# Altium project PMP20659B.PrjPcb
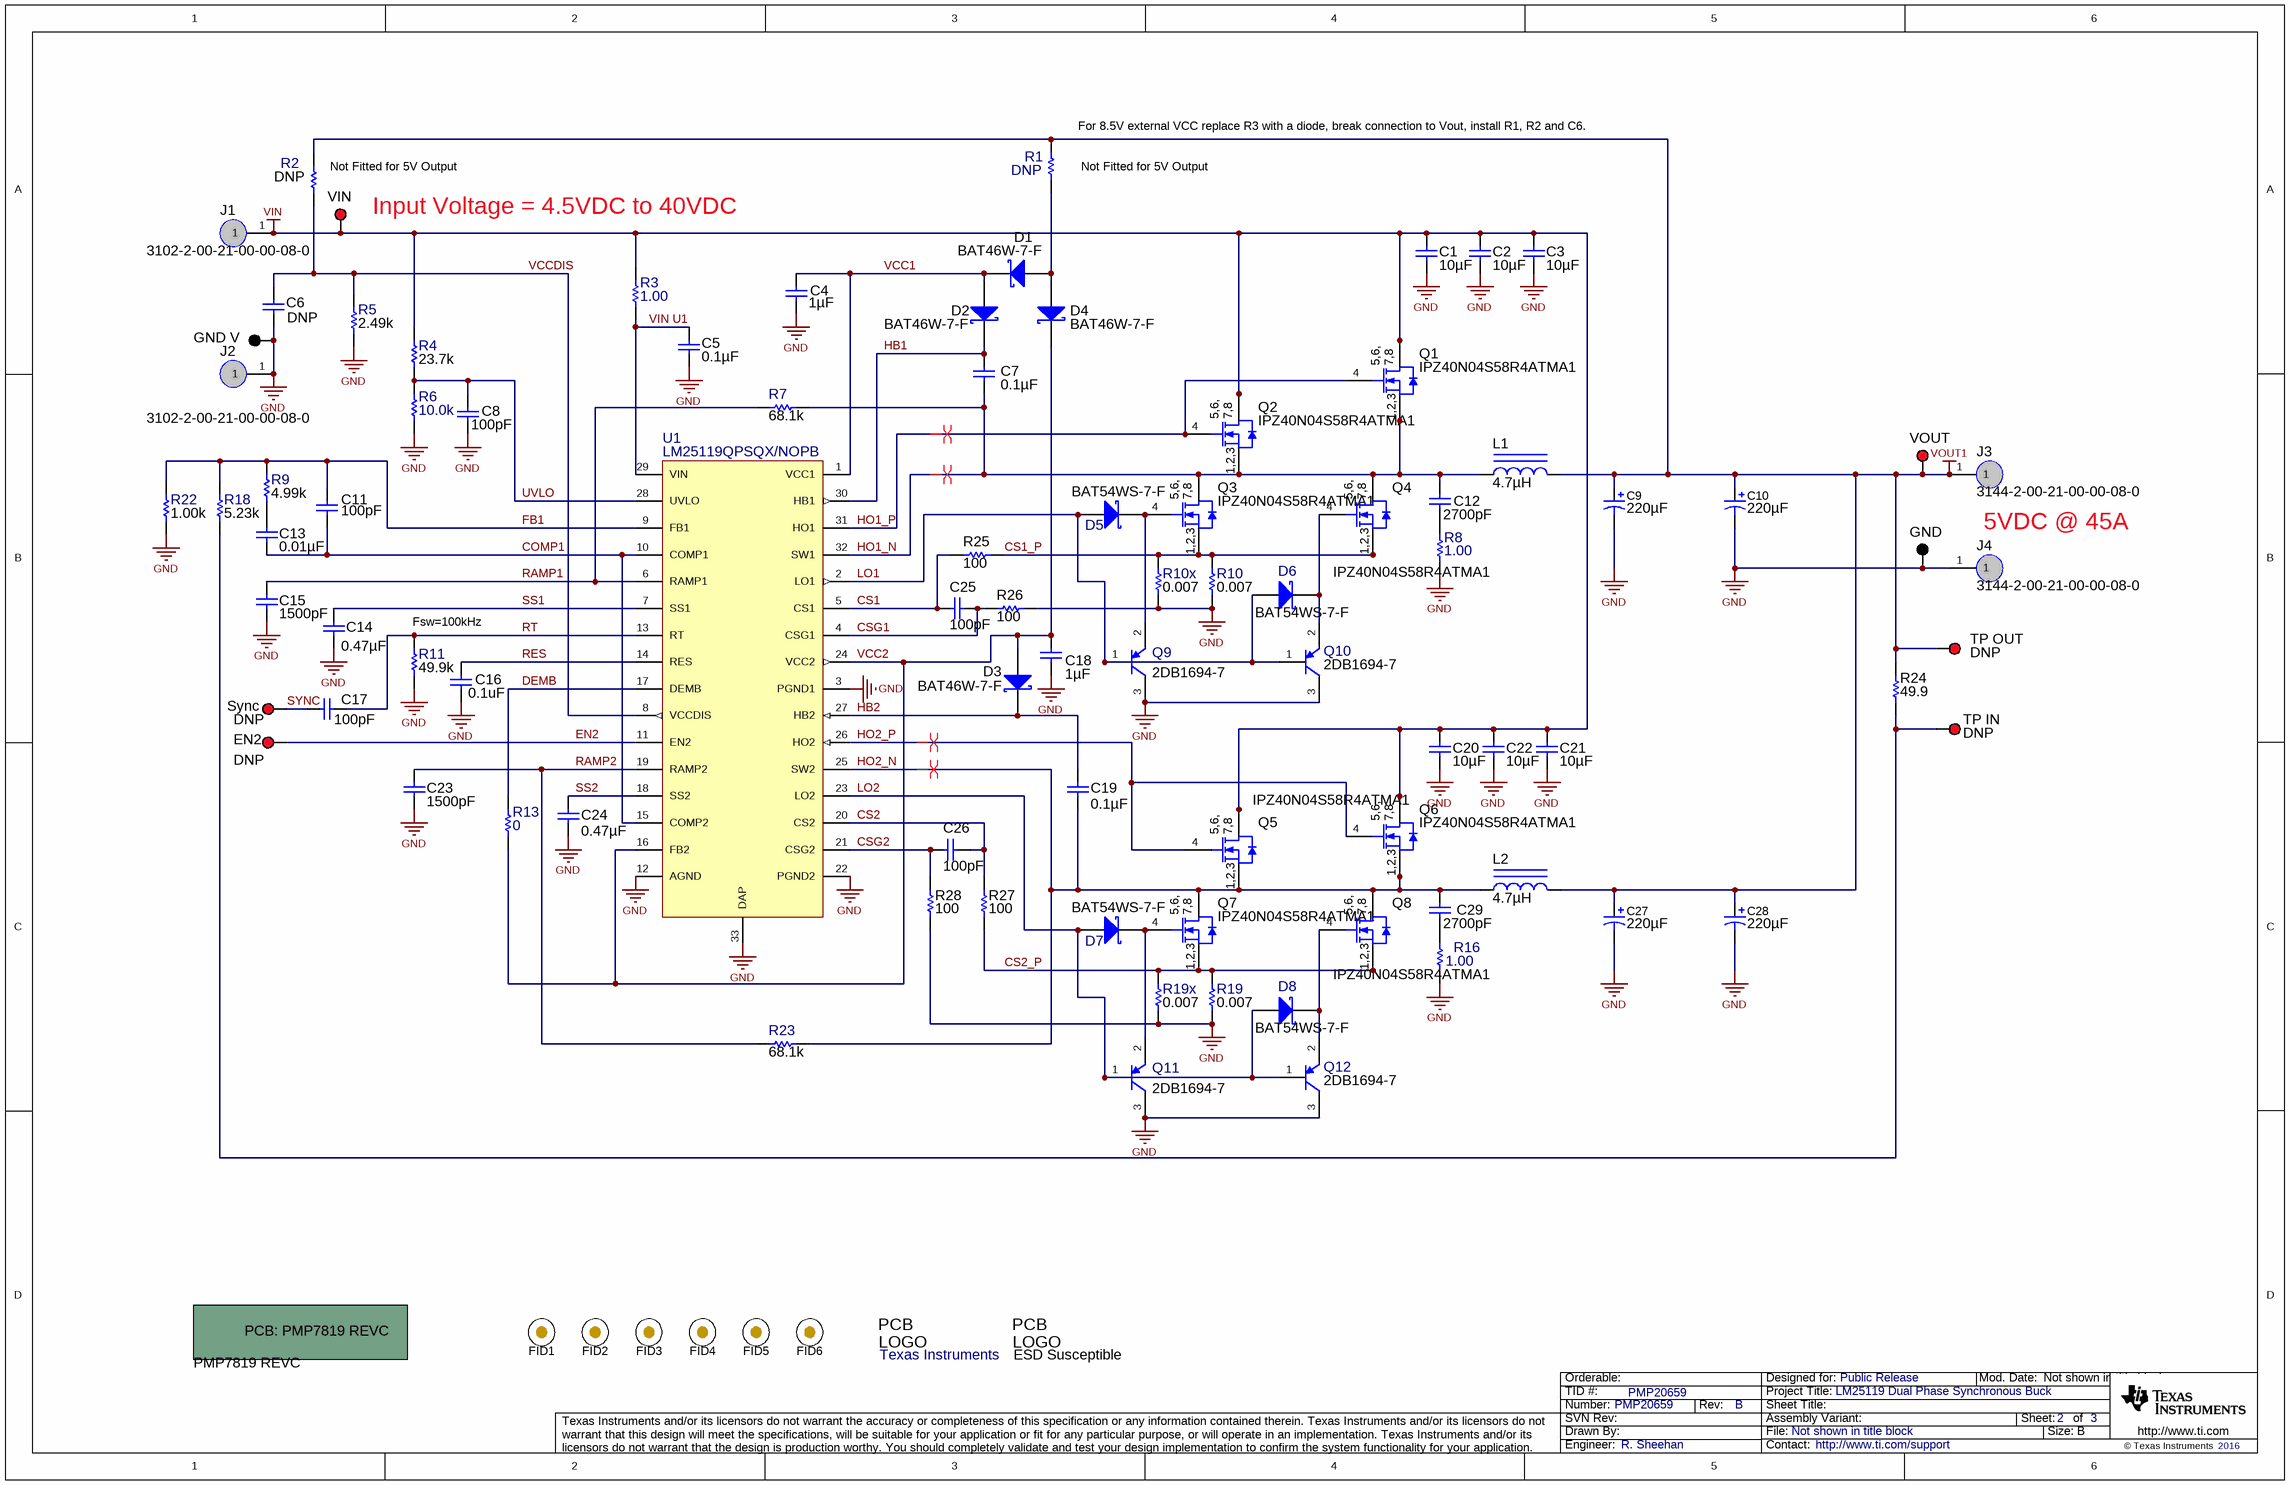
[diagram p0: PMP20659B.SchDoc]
TID: PMP20659; TechSupport: http://www.ti.com/support; SCH_Rev: B; PRJ_Title: LM25119 Dual Phase Synchronous Buck; PRJ_Number: PMP20659; PRJ_Engineer: R. Sheehan; PRJ_Customer: Public Release; PCB_Rev: C; CopyrightYear: 2016
1 sheet, 97 parts. Net scope: global (net labels, ports and power ports of the same name join across sheets).
Board file: PMP7819 REVC.PcbDoc

## Sheet PMP20659B.SchDoc
size 431 x 279 mm; Date: Not shown in title block; ApprovedBy: Not shown in title block; CheckedBy: Not shown in title block; Author: Not shown in title block; CompanyName: Not shown in title block; Engineer: Not shown in title block; Organization: Not shown in title block; Address1: Not shown in title block; Address2: Not shown in title block; Address3: Not shown in title block; Address4: Not shown in title block; DocumentNumber: 1; Revision: Use project parameter SCH_Rev; SheetNumber: 2; SheetTotal: 3; PageSetup: Record=PageOptions¦CenterHorizontal=True¦CenterVertical=True¦PrintScale=1.00¦XCorrection=1.00¦YCorrection=1.00¦PrintKind=0¦BorderSize=5000000¦LeftOffset=0¦BottomOffset=0¦Orientation=2¦PaperLength=1000¦PaperWidth=1000¦Scale=100¦PaperSource=15¦PrintQuality=600¦MediaType=1¦DitherType=10¦PaperKind=Letter¦PrintScaleMode=1

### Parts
!PCB?  PMP7819 REVC  (mechanical)
C1  ValueDisplayed: 10µF  [1210_280]  (hidden comment: UMK325AB7106KMHT)
C2  ValueDisplayed: 10µF  [1210_280]  (hidden comment: UMK325AB7106KMHT)
C3  ValueDisplayed: 10µF  [1210_280]  (hidden comment: UMK325AB7106KMHT)
C4  ValueDisplayed: 1µF  [0603]  (hidden comment: GRM188R71C105KA12D)
C5  ValueDisplayed: 0.1µF  [0805_HV]  (hidden comment: C2012X7R2A104K)
C6  DNP  [0603]
C7  ValueDisplayed: 0.1µF  [0603]  (hidden comment: GRM188R72A104KA35D)
C8  value 100pF  [0603]  (hidden comment: 06035A101JAT2A)
C9  ValueDisplayed: 220µF  [7343-31]  (hidden comment: T520D227M006ATE009)
C10  ValueDisplayed: 220µF  [7343-31]  (hidden comment: T520D227M006ATE009)
C11  value 100pF  [0603]  (hidden comment: 06035A101JAT2A)
C12  ValueDisplayed: 2700pF  [0603]  (hidden comment: 06031C272JAT2A)
C13  ValueDisplayed: 0.01µF  [0603]  (hidden comment: GCM188R71H103KA37D)
C14  ValueDisplayed: 0.47µF  [0603]  (hidden comment: GRM188R71E474KA12D)
C15  ValueDisplayed: 1500pF  [0603]  (hidden comment: GRM1885C1H152JA01D)
C16  value 0.1uF  [0603]  (hidden comment: C1608X7R1H104K)
C17  value 100pF  [0603]  (hidden comment: 06035A101JAT2A)
C18  ValueDisplayed: 1µF  [0603]  (hidden comment: GRM188R71C105KA12D)
C19  ValueDisplayed: 0.1µF  [0603]  (hidden comment: GRM188R72A104KA35D)
C20  ValueDisplayed: 10µF  [1210_280]  (hidden comment: UMK325AB7106KMHT)
C21  ValueDisplayed: 10µF  [1210_280]  (hidden comment: UMK325AB7106KMHT)
C22  ValueDisplayed: 10µF  [1210_280]  (hidden comment: UMK325AB7106KMHT)
C23  ValueDisplayed: 1500pF  [0603]  (hidden comment: GRM1885C1H152JA01D)
C24  ValueDisplayed: 0.47µF  [0603]  (hidden comment: GRM188R71E474KA12D)
C25  ValueDisplayed: 100pF  [0603]  (hidden comment: GRM1885C1H101JA01D)
C26  ValueDisplayed: 100pF  [0603]  (hidden comment: GRM1885C1H101JA01D)
C27  ValueDisplayed: 220µF  [7343-31]  (hidden comment: T520D227M006ATE009)
C28  ValueDisplayed: 220µF  [7343-31]  (hidden comment: T520D227M006ATE009)
C29  ValueDisplayed: 2700pF  [0603]  (hidden comment: 06031C272JAT2A)
D1  BAT46W-7-F  [SOD-123]
D2  BAT46W-7-F  [SOD-123]
D3  BAT46W-7-F  [SOD-123]
D4  BAT46W-7-F  [SOD-123]
D5  BAT54WS-7-F  [sod-323]
D6  BAT54WS-7-F  [sod-323]
D7  BAT54WS-7-F  [sod-323]
D8  BAT54WS-7-F  [sod-323]
EN2  DNP  [Keystone5000]
FID1  Fiducial  [Fiducial10-20]  (value not drawn)
FID2  Fiducial  [Fiducial10-20]  (value not drawn)
FID3  Fiducial  [Fiducial10-20]  (value not drawn)
FID4  Fiducial  [Fiducial10-20]  (value not drawn)
FID5  Fiducial  [Fiducial10-20]  (value not drawn)
FID6  Fiducial  [Fiducial10-20]  (value not drawn)
GND  5001  [Keystone5001]  (value not drawn)
GND_V  5001  [Keystone5001]  (value not drawn)
J1  3102-2-00-21-00-00-08-0  [3102-2-00-21-00-00-08-0]
J2  3102-2-00-21-00-00-08-0  [3102-2-00-21-00-00-08-0]
J3  3144-2-00-21-00-00-08-0  [3144-2-00-21-00-00-08-0]
J4  3144-2-00-21-00-00-08-0  [3144-2-00-21-00-00-08-0]
L1  ValueDisplayed: 4.7µH  [XAL1510]  (hidden comment: XAL1510-472MEB)
L2  ValueDisplayed: 4.7µH  [XAL1510]  (hidden comment: XAL1510-472MEB)
Logo1  Texas Instruments  [TI_Symbol_Overlay_Small]  (no BOM)
Logo2  ESD Susceptible  [ESD_Overlay_Small]  (no BOM)
Q1  IPZ40N04S58R4ATMA1  [PG-TSDSON-8]
Q2  IPZ40N04S58R4ATMA1  [PG-TSDSON-8]
Q3  IPZ40N04S58R4ATMA1  [PG-TSDSON-8]
Q4  IPZ40N04S58R4ATMA1  [PG-TSDSON-8]
Q5  IPZ40N04S58R4ATMA1  [PG-TSDSON-8]
Q6  IPZ40N04S58R4ATMA1  [PG-TSDSON-8]
Q7  IPZ40N04S58R4ATMA1  [PG-TSDSON-8]
Q8  IPZ40N04S58R4ATMA1  [PG-TSDSON-8]
Q9  2DB1694-7  [SOT-323 DIODES INC]
Q10  2DB1694-7  [SOT-323 DIODES INC]
Q11  2DB1694-7  [SOT-323 DIODES INC]
Q12  2DB1694-7  [SOT-323 DIODES INC]
R1  DNP  [0603]
R2  DNP  [0603]
R3  value 1.00  [0805_HV]  (hidden comment: CRCW08051R00FNEA)
R4  ValueDisplayed: 23.7k  [0603]  (hidden comment: CRCW060323K7FKEA)
R5  value 2.49k  [0603]  (hidden comment: CRCW06032K49FKEA)
R6  value 10.0k  [0603]  (hidden comment: CRCW060310K0FKEA)
R7  ValueDisplayed: 68.1k  [0603]  (hidden comment: CRCW060368K1FKEA)
R8  value 1.00  [1206]  (hidden comment: CRCW12061R00FNEA)
R9  ValueDisplayed: 4.99k  [0603]  (hidden comment: CRCW06034K99FKEA)
R10  ValueDisplayed: 0.007  [2010]  (hidden comment: WSL20107L000FEA18)
R10x  ValueDisplayed: 0.007  [2010]  (hidden comment: WSL20107L000FEA18)
R11  ValueDisplayed: 49.9k  [0603]  (hidden comment: CRCW060349K9FKEA)
R13  value 0  [0603]  (hidden comment: CRCW06030000Z0EA)
R16  value 1.00  [1206]  (hidden comment: CRCW12061R00FNEA)
R18  ValueDisplayed: 5.23k  [0603]  (hidden comment: CRCW06035K23FKEA)
R19  ValueDisplayed: 0.007  [2010]  (hidden comment: WSL20107L000FEA18)
R19x  ValueDisplayed: 0.007  [2010]  (hidden comment: WSL20107L000FEA18)
R22  ValueDisplayed: 1.00k  [0603]  (hidden comment: CRCW06031K00FKEA)
R23  ValueDisplayed: 68.1k  [0603]  (hidden comment: CRCW060368K1FKEA)
R24  value 49.9  [0603]  (hidden comment: CRCW060349R9FKEA)
R25  ValueDisplayed: 100  [0603]  (hidden comment: CRCW0603100RJNEA)
R26  ValueDisplayed: 100  [0603]  (hidden comment: CRCW0603100RJNEA)
R27  ValueDisplayed: 100  [0603]  (hidden comment: CRCW0603100RJNEA)
R28  ValueDisplayed: 100  [0603]  (hidden comment: CRCW0603100RJNEA)
Sync  DNP  [Keystone5000]
TP_IN  DNP  [Keystone5000]
TP_OUT  DNP  [Keystone5000]
U1  LM25119QPSQX/NOPB  [RTV0032A]
VIN  5000  [Keystone5000]  (value not drawn)
VOUT  5000  [Keystone5000]  (value not drawn)

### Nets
GND: C1.2 C2.2 C3.2 C4.2 C5.2 C6.2 C8.2 C9.2(-) C10.2(-) C14.2 C15.2 C16.2 C18.2 C20.2 C21.2 C22.2 C23.2 C24.2 C27.2(-) C28.2(-) GND.1 GND_V.1 J2.1 J4.1 Q9.3(C) Q10.3(C) Q11.3(C) Q12.3(C) R5.2 R6.1 R8.2 R10.1 R10x.1 R11.1 R16.2 R19.1 R19x.1 R22.1 R26.2 R28.1 U1.3(PGND1) U1.12(AGND) U1.22(PGND2) U1.33(DAP)
VIN: C1.1 C2.1 C3.1 C20.1 C21.1 C22.1 J1.1 Q1.5(D) Q1.6(D) Q1.7(D) Q1.8(D) Q1.9(D) Q2.5(D) Q2.6(D) Q2.7(D) Q2.8(D) Q2.9(D) Q5.5(D) Q5.6(D) Q5.7(D) Q5.8(D) Q5.9(D) Q6.5(D) Q6.6(D) Q6.7(D) Q6.8(D) Q6.9(D) R3.2 R4.2 VIN.1
VOUT1: C9.1(+) C10.1(+) C27.1(+) C28.1(+) J3.1 L1.2 L2.2 R1.1 R2.2 R24.2 TP_OUT.1 VOUT.1
COMP1: C11.2 C13.2 U1.10(COMP1) U1.15(COMP2)
CS1: C25.2 R25.1 U1.5(CS1)
CS1_P: Q3.1(S) Q3.2(S) Q3.3(S) Q4.1(S) Q4.2(S) Q4.3(S) R10.2 R10x.2 R25.2
CS2: C26.1 R27.2 U1.20(CS2)
CS2_P: Q7.1(S) Q7.2(S) Q7.3(S) Q8.1(S) Q8.2(S) Q8.3(S) R19.2 R19x.2 R27.1
CSG1: C25.1 R26.1 U1.4(CSG1)
CSG2: C26.2 R28.2 U1.21(CSG2)
DEMB: R13.2 U1.17(DEMB)
EN2: EN2.1 U1.11(EN2)
FB1: C11.1 R9.2 R18.1 R22.2 U1.9(FB1)
HB1: C7.2 D2.1(K) U1.30(HB1)
HB2: C19.1 D3.1(K) U1.27(HB2)
HO1_N: C7.1 C12.1 L1.1 Q1.1(S) Q1.2(S) Q1.3(S) Q2.1(S) Q2.2(S) Q2.3(S) Q3.5(D) Q3.6(D) Q3.7(D) Q3.8(D) Q3.9(D) Q4.5(D) Q4.6(D) Q4.7(D) Q4.8(D) Q4.9(D) R7.2 U1.32(SW1)
HO1_P: Q1.4(G) Q2.4(G) U1.31(HO1)
HO2_N: C19.2 C29.1 L2.1 Q5.1(S) Q5.2(S) Q5.3(S) Q6.1(S) Q6.2(S) Q6.3(S) Q7.5(D) Q7.6(D) Q7.7(D) Q7.8(D) Q7.9(D) Q8.5(D) Q8.6(D) Q8.7(D) Q8.8(D) Q8.9(D) R23.2 U1.25(SW2)
HO2_P: Q5.4(G) Q6.4(G) U1.26(HO2)
LO1: D5.2(A) D6.2(A) Q9.1(B) Q10.1(B) U1.2(LO1)
LO2: D7.2(A) D8.2(A) Q11.1(B) Q12.1(B) U1.23(LO2)
RAMP1: C15.1 R7.1 U1.6(RAMP1)
RAMP2: C23.1 R23.1 U1.19(RAMP2)
RES: C16.1 U1.14(RES)
RT: C17.2 R11.2 U1.13(RT)
SS1: C14.1 U1.7(SS1)
SS2: C24.1 U1.18(SS2)
SYNC: C17.1 Sync.1
UVLO: C8.1 R4.1 R6.2 U1.28(UVLO)
VCC1: C4.1 D1.1(K) D2.2(A) U1.1(VCC1)
VCC2: C18.1 D3.2(A) D4.1(K) R13.1 U1.16(FB2) U1.24(VCC2)
VCCDIS: C6.1 R2.1 R5.1 U1.8(VCCDIS)
VIN U1: C5.1 R3.1 U1.29(VIN)
NetC12_2: C12.2 R8.1
NetC13_1: C13.1 R9.1
NetC29_2: C29.2 R16.1
NetD1_2: D1.2(A) D4.2(A) R1.2
NetD5_1: D5.1(K) Q3.4(G) Q9.2(E)
NetD6_1: D6.1(K) Q4.4(G) Q10.2(E)
NetD7_1: D7.1(K) Q7.4(G) Q11.2(E)
NetD8_1: D8.1(K) Q8.4(G) Q12.2(E)
NetR18_2: R18.2 R24.1 TP_IN.1

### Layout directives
differential pair: HO1_N, HO1_P, HO2_N, HO2_P

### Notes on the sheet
- (near R2) Not Fitted for 5V Output
- (near R1) Not Fitted for 5V Output
- (near R1) For 8.5V external VCC replace R3 with a diode, break connection to Vout, install R1, R2 and C6.
- (near VIN) Input Voltage = 4.5VDC to 40VDC
- 5VDC @ 45A
- (near R11) Fsw=100kHz

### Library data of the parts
!PCB? = PCB_OtherProject: Manufacturer: Any; SymbolCreator: a0412235; CompType: PCB; U/M: EA
C1-C3 C20-C22 = UMK325AB7106KMHT: CAP, CERM, 10 µF, 50 V, +/- 10%, X7R, AEC-Q200 Grade 1, 1210; Manufacturer: Taiyo Yuden; Cap_Case: 1210; Polarized: N; TaMax_C: 125; TaMin_C: -55; Tolerance_%: 10; VDC_V: 50; Cap_F: 0.00001; CompType: Capacitor; Value: 10uF; Value1: Unknown; Value2: 50V; U/M: EA; SizeArea_mm2: 8; SizeAreaWB_mm2: 14.7; SizeX_mm: 3.2; SizeY_mm: 2.5; SizeZ_mm: 2.8; AEC Category: Q200; AEC Qualified: Y; AEC Grade: 1
C4 C18 = GRM188R71C105KA12D: CAP, CERM, 1uF, 16V, +/-10%, X7R, 0603; Manufacturer: MuRata; ESR_Ohm: 0.011; Polarized: N; TaMax_C: 125; TaMin_C: -55; Tolerance_%: 10; VDC_V: 16; Cap_F: 0.000001; CompType: Capacitor; U/M: EA; Value1: 0.011 ohm
C5 = C2012X7R2A104K: CAP, CERM, 0.1uF, 100V, +/-10%, X7R, 0805; Manufacturer: TDK; Cap_Case: 0805; ESR_Ohm: 0.0158; Polarized: N; TaMax_C: 125; TaMin_C: -55; Tolerance_%: 10; VDC_V: 100; Cap_F: 0.0000001; CompType: Capacitor; Value1: 0.0158 ohm; U/M: EA
C6 C16 = C1608X7R1H104K: CAP, CERM, 0.1uF, 50V, +/-10%, X7R, 0603; Manufacturer: TDK; ESR_Ohm: 0.017; Polarized: N; TaMax_C: 125; TaMin_C: -55; Tolerance_%: 10; VDC_V: 50; Cap_F: 0.0000001; CompType: Capacitor; Value1: 0.017 ohm; U/M: EA; ValueDisplayed: 0.1µF
C7 C19 = GRM188R72A104KA35D: CAP, CERM, 0.1uF, 100V, +/-10%, X7R, 0603; Manufacturer: MuRata; Polarized: N; TaMax_C: 125; TaMin_C: -55; Tolerance_%: 10; VDC_V: 100; Cap_F: 0.0000001; CompType: Capacitor; U/M: EA
C8 C11 C17 = 06035A101JAT2A: CAP, CERM, 100pF, 50V, +/-5%, C0G/NP0, 0603; Manufacturer: AVX; ESR_Ohm: 0.119; Polarized: N; TaMax_C: 125; TaMin_C: -55; Tolerance_%: 5; VDC_V: 50; Cap_F: 0.0000000001; CompType: Capacitor; Value1: 0.119 ohm; U/M: EA
C9 C10 C27 C28 = T520D227M006ATE009: CAP, TA, 220 µF, 6.3 V, +/- 20%, 0.009 ohm, SMD; Manufacturer: Kemet; Polarized: Y; CompType: Capacitor; Value: 220uF; U/M: EA; Cap_F: 0.00022; Tolerance_%: 20; VDC_V: 6.3; Value2: 6.3V; ESR_ohm: 0.009; TaMin_C: -55; TaMax_C: 105; Cap_Case: D; SizeAreaWB_mm2: 58.59; SizeArea_mm2: 31.39; SizeX_mm: 7.3; SizeY_mm: 4.3; SizeZ_mm: 3.1; AEC Category: Q200; AEC Qualified: N
C12 C29 = 06031C272JAT2A: CAP, CERM, 2700pF, 100V, +/-5%, X7R, 0603; Manufacturer: AVX; ESR_Ohm: 0.174; Polarized: N; TaMax_C: 125; TaMin_C: -55; Tolerance_%: 5; VDC_V: 100; Cap_F: 0.0000000027; CompType: Capacitor; Value1: 0.174 ohm; U/M: EA
C13 = GCM188R71H103KA37D: CAP, CERM, 0.01 µF, 50 V, +/- 10%, X7R, AEC-Q200 Grade 1, 0603; Manufacturer: MuRata; Polarized: N; TaMax_C: 125; TaMin_C: -55; Tolerance_%: 10; VDC_V: 50; Cap_F: 0.00000001; CompType: Capacitor; Value: 0.01uF; Value1: Unknown; Value2: 50V; U/M: EA; SizeArea_mm2: 1.28; SizeAreaWB_mm2: 4.68; SizeX_mm: 1.6; SizeY_mm: 0.8; SizeZ_mm: 1; AEC Category: Q200; AEC Qualified: Y
C14 C24 = GRM188R71E474KA12D: CAP, CERM, 0.47uF, 25V, +/-10%, X7R, 0603; Manufacturer: MuRata; Polarized: N; TaMax_C: 125; TaMin_C: -55; Tolerance_%: 10; VDC_V: 25; Cap_F: 0.00000047; CompType: Capacitor; Value1: Unknown; U/M: EA
C15 C23 = GRM1885C1H152JA01D: CAP, CERM, 1500 pF, 50 V, +/- 5%, C0G/NP0, 0603; Manufacturer: MuRata; Polarized: N; TaMax_C: 125; TaMin_C: -55; Tolerance_%: 5; VDC_V: 50; Cap_F: 0.0000000015; CompType: Capacitor; Value: 1500pF; Value1: Unknown; Value2: 50V; U/M: EA; SizeArea_mm2: 1.28; SizeAreaWB_mm2: 4.68; SizeX_mm: 1.6; SizeY_mm: 0.8; SizeZ_mm: 1; AEC Category: Q200
C25 C26 = GRM1885C1H101JA01D: CAP, CERM, 100 pF, 50 V, +/- 5%, C0G/NP0, 0603; Manufacturer: MuRata; Polarized: N; CompType: Capacitor; Value: 100pF; U/M: EA; Cap_F: 0.0000000001; Tolerance_%: 5; Value1: Unknown; VDC_V: 50; Value2: 50V; TaMin_C: -55; TaMax_C: 125; SizeArea_mm2: 1.28; SizeAreaWB_mm2: 4.68; SizeX_mm: 1.6; SizeY_mm: 0.8; SizeZ_mm: 1; AEC Category: Q200
D1-D4 = BAT46W-7-F: Diode, Schottky, 100V, 0.15A, SOD-123; Manufacturer: Diodes Inc.; Vf_V: 0.6; Io_A: 0.15; Vr_V: 100; Value: 0.6V; U/M: EA
D5-D8 = BAT54WS-7-F: Diode, Schottky, 30V, 0.2A, SOD-323; Manufacturer: Diodes Inc.; Value: 0.7V; U/M: EA; Vf_V: 0.7; Io_A: 0.2; Vr_V: 30; TJmax_C: 125
EN2 Sync TP_IN TP_OUT VIN VOUT = 5000: Test Point, TH, Miniature, Red; Manufacturer: Keystone; CompType: Test Point Loop; U/M: EA
FID1-FID6 = Fiducial: Fiducial mark.  There is nothing to buy or mount.; SymbolCreator: codlsc
GND GND_V = 5001: Test Point, TH, Miniature, Black; Manufacturer: Keystone; CompType: Test Point Loop; U/M: EA
J1 J2 = 3102-2-00-21-00-00-08-0: PC PIN .040 DIA 3102-2 SERIES; Manufacturer: Mill -Max; SymbolVersion: 2011 - 12 - 16; SymbolCreator: cdnlsc; U/M: EA
J3 J4 = 3144-2-00-21-00-00-08-0: CIRCUIT PIN PRNTD .188" .084"; Manufacturer: Mill -Max; SymbolVersion: 2011 - 12 - 16; SymbolCreator: cdnlsc; U/M: EA
L1 L2 = XAL1510-472MEB: Inductor, Shielded, Composite, 4.7 µH, 29 A, 0.00335 ohm, SMD; Manufacturer: Coilcraft; Value: 4.7uH; Ind_H: 4.7E-6; Imax_A: 29; Irms: 29A @ 40C rise; Isat: 39A @ 30% inductance drop; Value2: 29A; SizeAreaWB_mm2: 320.16; SizeArea_mm2: 252.56; SizeX_mm: 16.4; SizeY_mm: 15.4; SizeZ_mm: 10; AEC Category: Q200
Logo1 = TI_Logo: Texas Instrument Corporate Signature; SymbolCreator: codlsc
Logo2 = ESD_Susceptible: ESD Susceptible Symbol; SymbolCreator: codlsc
Q1-Q8 = IPZ40N04S58R4ATMA1: MOSFET, N-CH, 40 V, 40 A, AEC-Q101, PG-TSDSON-8; Manufacturer: Infineon Technologies; Alternate Manufacturer: None; Value: 40V; ChType: N; VdsMax_V: 40; Value1: ? ohm; Value2: 10.3 nC; QgTyp_nC: 10.3; Vgs_V: 20; U/M: EA; SizeAreaWB_mm2: 19.36; SizeArea_mm2: 11.56; SizeX_mm: 3.4; SizeZ_mm: 1.1; AEC Category: Q101; AEC Qualified: Y
Q9-Q12 = 2DB1694-7: TRANS BIPO PNP 30V 1A SOT-323; Manufacturer: Diodes Inc.; CompType: BJT; U/M: EA; PNP: 1; NPN: 0; Vceo_V: 30; Vcesat1_V: 0.075; Value: 0.075V; IcRated_A: 0.1; Value1: 0.1A; HfeMax: 600
R1 = CRCW06030000Z0EA: RES, 0 ohm, 5%, 0.1W, 0603; Manufacturer: Vishay-Dale; CompType: Resistor; Tolerance_%: 5; VDC_V: 75; Power_W: 0.1; Res_Ohm: 0; Value: 0; Value_Code: 0000; EIA_Code: E24; U/M: EA
R2 = CRCW060310K0FKEA: RES, 10.0k ohm, 1%, 0.1W, 0603; Manufacturer: Vishay-Dale; CompType: Resistor; Tolerance_%: 1; VDC_V: 75; Power_W: 0.1; Res_ohm: 10000; Value_Code: 10k0; EIA_Code: E96; U/M: EA; TempCo: 100 ppm/C
R3 = CRCW08051R00FNEA: RES, 1.00 ohm, 1%, 0.125W, 0805; Manufacturer: Vishay-Dale; CompType: Resistor; Tolerance_%: 1; VDC_V: 150; Power_W: 0.125; Value_Code: 1R00; EIA_Code: E96; U/M: EA
R4 = CRCW060323K7FKEA: RES, 23.7 k, 1%, 0.1 W, 0603; Manufacturer: Vishay-Dale; CompType: Resistor; Tolerance_%: 1; VDC_V: 75; Power_W: 0.1; Res_ohm: 23700; Value: 23.7k; Value_Code: 23k7; Value2: 0.1W; EIA_Code: E96; U/M: EA; TempCo: 100 ppm/C; SizeArea_mm2: 1.28; SizeX_mm: 1.6; SizeY_mm: 0.8; AEC Category: Q200
R5 = CRCW06032K49FKEA: RES, 2.49k ohm, 1%, 0.1W, 0603; Manufacturer: Vishay-Dale; CompType: Resistor; Tolerance_%: 1; VDC_V: 75; Power_W: 0.1; Res_ohm: 2490; Value_Code: 2k49; EIA_Code: E96; U/M: EA; TempCo: 100 ppm/C
R6 = CRCW060310K0FKEA: RES, 10.0k ohm, 1%, 0.1W, 0603; Manufacturer: Vishay-Dale; CompType: Resistor; Tolerance_%: 1; VDC_V: 75; Power_W: 0.1; Res_Ohm: 10000; Value_Code: 10k0; EIA_Code: E96; U/M: EA
R7 R23 = CRCW060368K1FKEA: RES, 68.1 k, 1%, 0.1 W, 0603; Manufacturer: Vishay-Dale; CompType: Resistor; Tolerance_%: 1; VDC_V: 75; Power_W: 0.1; Res_ohm: 68100; Value: 68.1k; Value_Code: 68k1; Value2: 0.1W; EIA_Code: E96; U/M: EA; TempCo: 100 ppm/C; SizeArea_mm2: 1.28; SizeX_mm: 1.6; SizeY_mm: 0.8; AEC Category: Q200
R8 R16 = CRCW12061R00FNEA: RES, 1.00 ohm, 1%, 0.25W, 1206; Manufacturer: Vishay-Dale; CompType: Resistor; Tolerance_%: 1; VDC_V: 200; Power_W: 0.25; Value_Code: 1R00; EIA_Code: E96; U/M: EA
R9 = CRCW06034K99FKEA: RES, 4.99 k, 1%, 0.1 W, 0603; Manufacturer: Vishay-Dale; CompType: Resistor; Tolerance_%: 1; VDC_V: 75; Power_W: 0.1; Res_ohm: 4990; Value: 4.99k; Value_Code: 4k99; Value2: 0.1W; EIA_Code: E96; U/M: EA; TempCo: 100 ppm/C; SizeArea_mm2: 1.28; SizeX_mm: 1.6; SizeY_mm: 0.8; AEC Category: Q200
R10 R10x R19 R19x = WSL20107L000FEA18: RES, 0.007, 1%, 1 W, 2010; Manufacturer: Vishay-Dale; CompType: Resistor; Tolerance_%: 1; Value: 0.007; Value_Code: 7L000; Value2: 1W; EIA_Code: E96; U/M: EA; TempCo: 75 ppm/C; SizeArea_mm2: 12.5; SizeX_mm: 5; SizeY_mm: 2.5; SizeZ_mm: 1.66; AEC Category: Q200
R11 = CRCW060349K9FKEA: RES, 49.9 k, 1%, 0.1 W, 0603; Manufacturer: Vishay-Dale; CompType: Resistor; Tolerance_%: 1; VDC_V: 75; Power_W: 0.1; Res_ohm: 49900; Value: 49.9k; Value_Code: 49k9; Value2: 0.1W; EIA_Code: E96; U/M: EA; TempCo: 100 ppm/C; SizeArea_mm2: 1.28; SizeX_mm: 1.6; SizeY_mm: 0.8; AEC Category: Q200
R13 = CRCW06030000Z0EA: RES, 0 ohm, 5%, 0.1W, 0603; Manufacturer: Vishay-Dale; CompType: Resistor; Tolerance_%: 5; VDC_V: 75; Power_W: 0.1; Value_Code: 0000; EIA_Code: E24; U/M: EA
R18 = CRCW06035K23FKEA: RES, 5.23 k, 1%, 0.1 W, 0603; Manufacturer: Vishay-Dale; CompType: Resistor; Tolerance_%: 1; VDC_V: 75; Power_W: 0.1; Res_ohm: 5230; Value: 5.23k; Value_Code: 5k23; Value2: 0.1W; EIA_Code: E96; U/M: EA; TempCo: 100 ppm/C; SizeArea_mm2: 1.28; SizeX_mm: 1.6; SizeY_mm: 0.8; AEC Category: Q200
R22 = CRCW06031K00FKEA: RES, 1.00 k, 1%, 0.1 W, 0603; Manufacturer: Vishay-Dale; CompType: Resistor; Tolerance_%: 1; VDC_V: 75; Power_W: 0.1; Res_ohm: 1000; Value_Code: 1k00; Value2: 0.1W; EIA_Code: E96; Value: 1.00k; U/M: EA; TempCo: 100 ppm/C; SizeArea_mm2: 1.28; SizeX_mm: 1.6; SizeY_mm: 0.8; AEC Category: Q200
R24 = CRCW060349R9FKEA: RES, 49.9 ohm, 1%, 0.1W, 0603; Manufacturer: Vishay-Dale; CompType: Resistor; Value_Code: 49R9; Tolerance_%: 1; Power_W: 0.1; VDC_V: 75; TempCo: 100 ppm/C; EIA_Code: E96; U/M: EA
R25-R28 = CRCW0603100RJNEA: RES, 100, 5%, 0.1 W, 0603; Manufacturer: Vishay-Dale; CompType: Resistor; Value: 100; Value_Code: 100R; Tolerance_%: 5; Power_W: 0.1; Value2: 0.1W; VDC_V: 75; TempCo: 200 ppm/C; EIA_Code: E24; U/M: EA; SizeArea_mm2: 1.28; SizeX_mm: 1.6; SizeY_mm: 0.8; SizeZ_mm: 1; AEC Category: Q200
U1 = LM25119QPSQX/NOPB: Wide Input Range, Dual Synchronous Buck Controller, RTV0032A (WQFN-32); Manufacturer: Texas Instruments; Alternate PartNumber: LM25119QPSQ/NOPB; CompType: IC; SizeArea_mm2: 25; SizeAreaWB_mm2: 49; SizeX_mm: 5; SizeZ_mm: 0.8; SymbolCreator: a0411947; U/M: EA

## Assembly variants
001: not fitted C6 EN2 FID1 FID2 FID3 FID4 FID5 FID6 R1 R2 Sync TP IN TP OUT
